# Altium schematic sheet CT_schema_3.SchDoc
size 312 x 238 mm
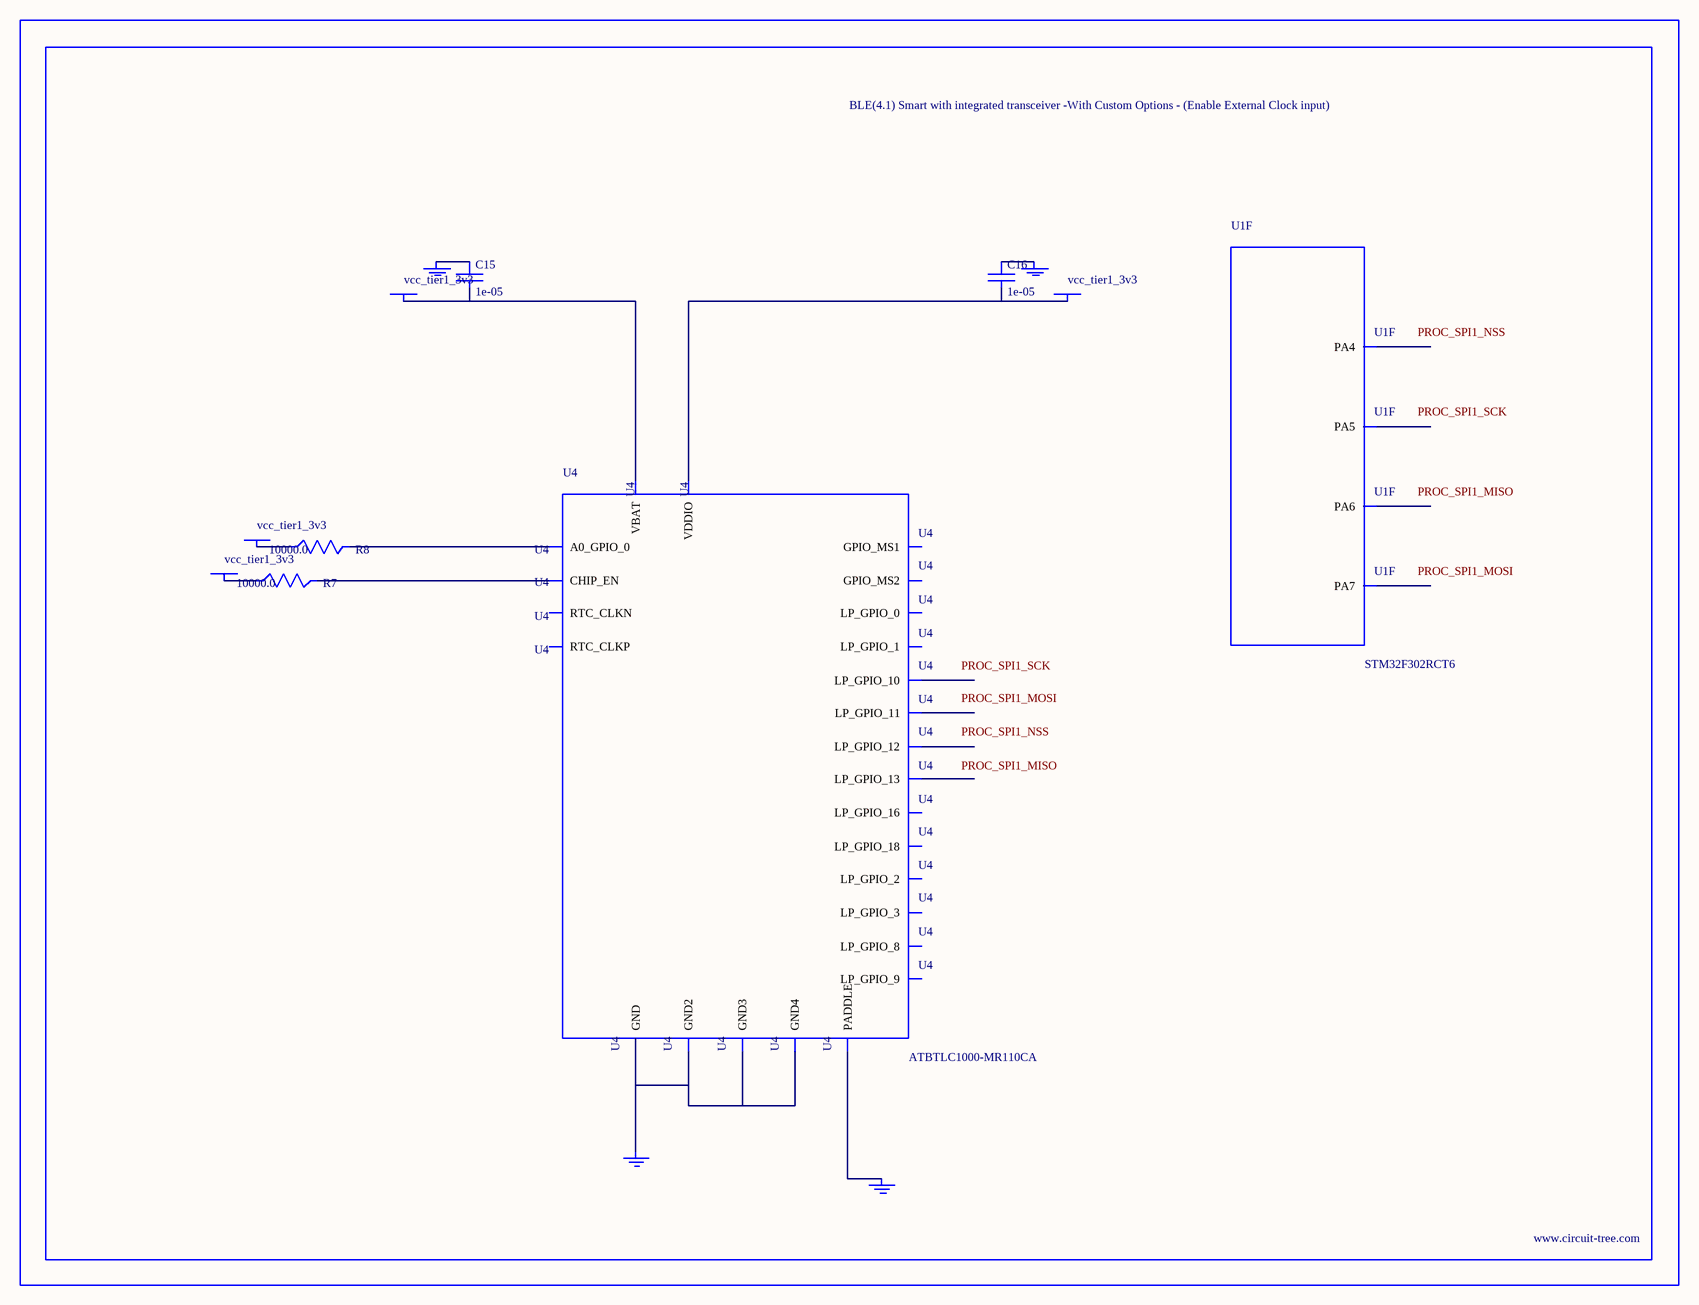
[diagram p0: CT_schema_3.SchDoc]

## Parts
BORDER2  (no value)
C15  1e-05  [C0805]
C16  1e-05  [C0805]
GND_INSTANCE_2_0  (no value)
GND_INSTANCE_2_1  (no value)
GND_INSTANCE_2_2  (no value)
GND_INSTANCE_2_3  (no value)
POWER_INSTANCE_2_0  vcc_tier1_3v3
POWER_INSTANCE_2_1  vcc_tier1_3v3
POWER_INSTANCE_2_2  vcc_tier1_3v3
POWER_INSTANCE_2_3  vcc_tier1_3v3
R7  10000.0  [R0603]
R8  10000.0  [R0603]
U1  STM32F302RCT6  [LQFP64]  (part F of 8)
U4  ATBTLC1000-MR110CA  [ATBTLC1000-MR110CA]

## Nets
NetC15_1: C15.1 GND_INSTANCE_2_0.0(GND)
NetC15_2: C15.2 POWER_INSTANCE_2_0.0(PWR) U4.6(VBAT)
NetC16_1: C16.1 GND_INSTANCE_2_1.0(GND)
NetC16_2: C16.2 POWER_INSTANCE_2_3.0(PWR) U4.22(VDDIO)
NetGND_INSTANCE_2_2_0: GND_INSTANCE_2_2.0(GND) U4.25(PADDLE)
NetGND_INSTANCE_2_3_0: GND_INSTANCE_2_3.0(GND) U4.1(GND) U4.9(GND2) U4.13(GND3) U4.24(GND4)
NetPOWER_INSTANCE_2_1_0: POWER_INSTANCE_2_1.0(PWR) R7.1
NetPOWER_INSTANCE_2_2_0: POWER_INSTANCE_2_2.0(PWR) R8.1
NetR7_2: R7.2 U4.17(CHIP_EN)
NetR8_2: R8.2 U4.20(A0_GPIO_0)

Not connected (* = marked no-connect by the designer): U1 20(PA4) 21(PA5) 22(PA6) 23(PA7); U4 2(LP_GPIO_0) 3(LP_GPIO_1) 4(LP_GPIO_2) 5(LP_GPIO_3) 7(LP_GPIO_8) 8(LP_GPIO_9) 10(LP_GPIO_10) 11(LP_GPIO_11) 12(LP_GPIO_12) 14(LP_GPIO_13) 15(GPIO_MS1) 16(GPIO_MS2) 18(RTC_CLKP) 19(RTC_CLKN) 21(LP_GPIO_16) 23(LP_GPIO_18)

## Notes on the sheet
- Labels drawn without touching a wire or pin: PROC_SPI1_MISO, PROC_SPI1_MOSI, PROC_SPI1_NSS, PROC_SPI1_SCK

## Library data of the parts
BORDER2 = BORDER_PAGE2
C15 C16 = C0805C106K8RACTU
GND_INSTANCE_2_0-GND_INSTANCE_2_3 = GND
POWER_INSTANCE_2_0-POWER_INSTANCE_2_3 = PWR
R7 R8 = RC0603JR-0710KL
